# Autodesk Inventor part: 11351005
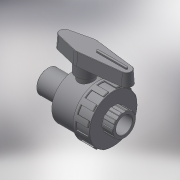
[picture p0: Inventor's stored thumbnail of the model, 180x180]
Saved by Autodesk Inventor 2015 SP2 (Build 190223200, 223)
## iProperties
Created: 2017-11
Part Number: 11351005
Material: Generic
Description: PLASSON 1/NUT VALVE FEMALE THREADED 1/2" PVC
Document SubType Name: Modeling
Designer: KIM
Density: 1 g/cm^3
Appearance: Default
Author: KIM
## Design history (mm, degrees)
derived "113510.ipt"
feature "Solid1::113510.ipt"
tag "TaggingFeature1"
body "Solid1"
other parameters: "d0" = 73, "d2" = 45, "d4" = 14.9048, "d8" = 40.5, "d13" = 0.55893, "d25" = 0.37262, "d26" = 0.55893, "d29" = 12, "d30" = 0, "d35" = 0.55893, "d39" = 22.5, "d45" = 360 deg, "d47" = 0.37262, "d50" = 24.75, "d51" = 13.5, "d53" = 0, "d55" = 3.7262, "d56" = 1.8631, "d57" = 11.2, "d58" = 0, "d59" = 0.55893, "d63" = 18, "d64" = 45, "d66" = 65, "d68" = 9, "d69" = 19.5, "d70" = 11.25, "d71" = 3 deg, "d73" = 0.9, "d74" = 26, "d75" = 1.35, "d76" = 0, "d77" = 0.37262, "d78" = 18.631, "d79" = 16, "d80" = 45, "d81" = 16, "d82" = 43.2, "d83" = 11.2, "d84" = 26.0834, "d85" = 18.631, "d86" = 26.0834, "d87" = 120 deg, "d88" = 16, "d90" = 360 deg, "d92" = 6.75, "d95" = 3.375, "G_" = 18.631, "l_" = 16, "H_" = 73, "K_" = 45, "F_" = 45, "J_" = 65, "d67" = 18, "d72" = 4.5
